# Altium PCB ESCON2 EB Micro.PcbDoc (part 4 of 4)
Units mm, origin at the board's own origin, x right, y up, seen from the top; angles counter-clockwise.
Board outline 75.6 x 72 mm, 8 copper layers (Top Side, Mid Layer 1, Mid Layer 2, Mid Layer 3, Mid Layer 4, Mid Layer 5, Mid Layer 6, Bottom Side), stack 1.555 mm thick; 192 components, 85 nets, 547 pads, 2387 vias.
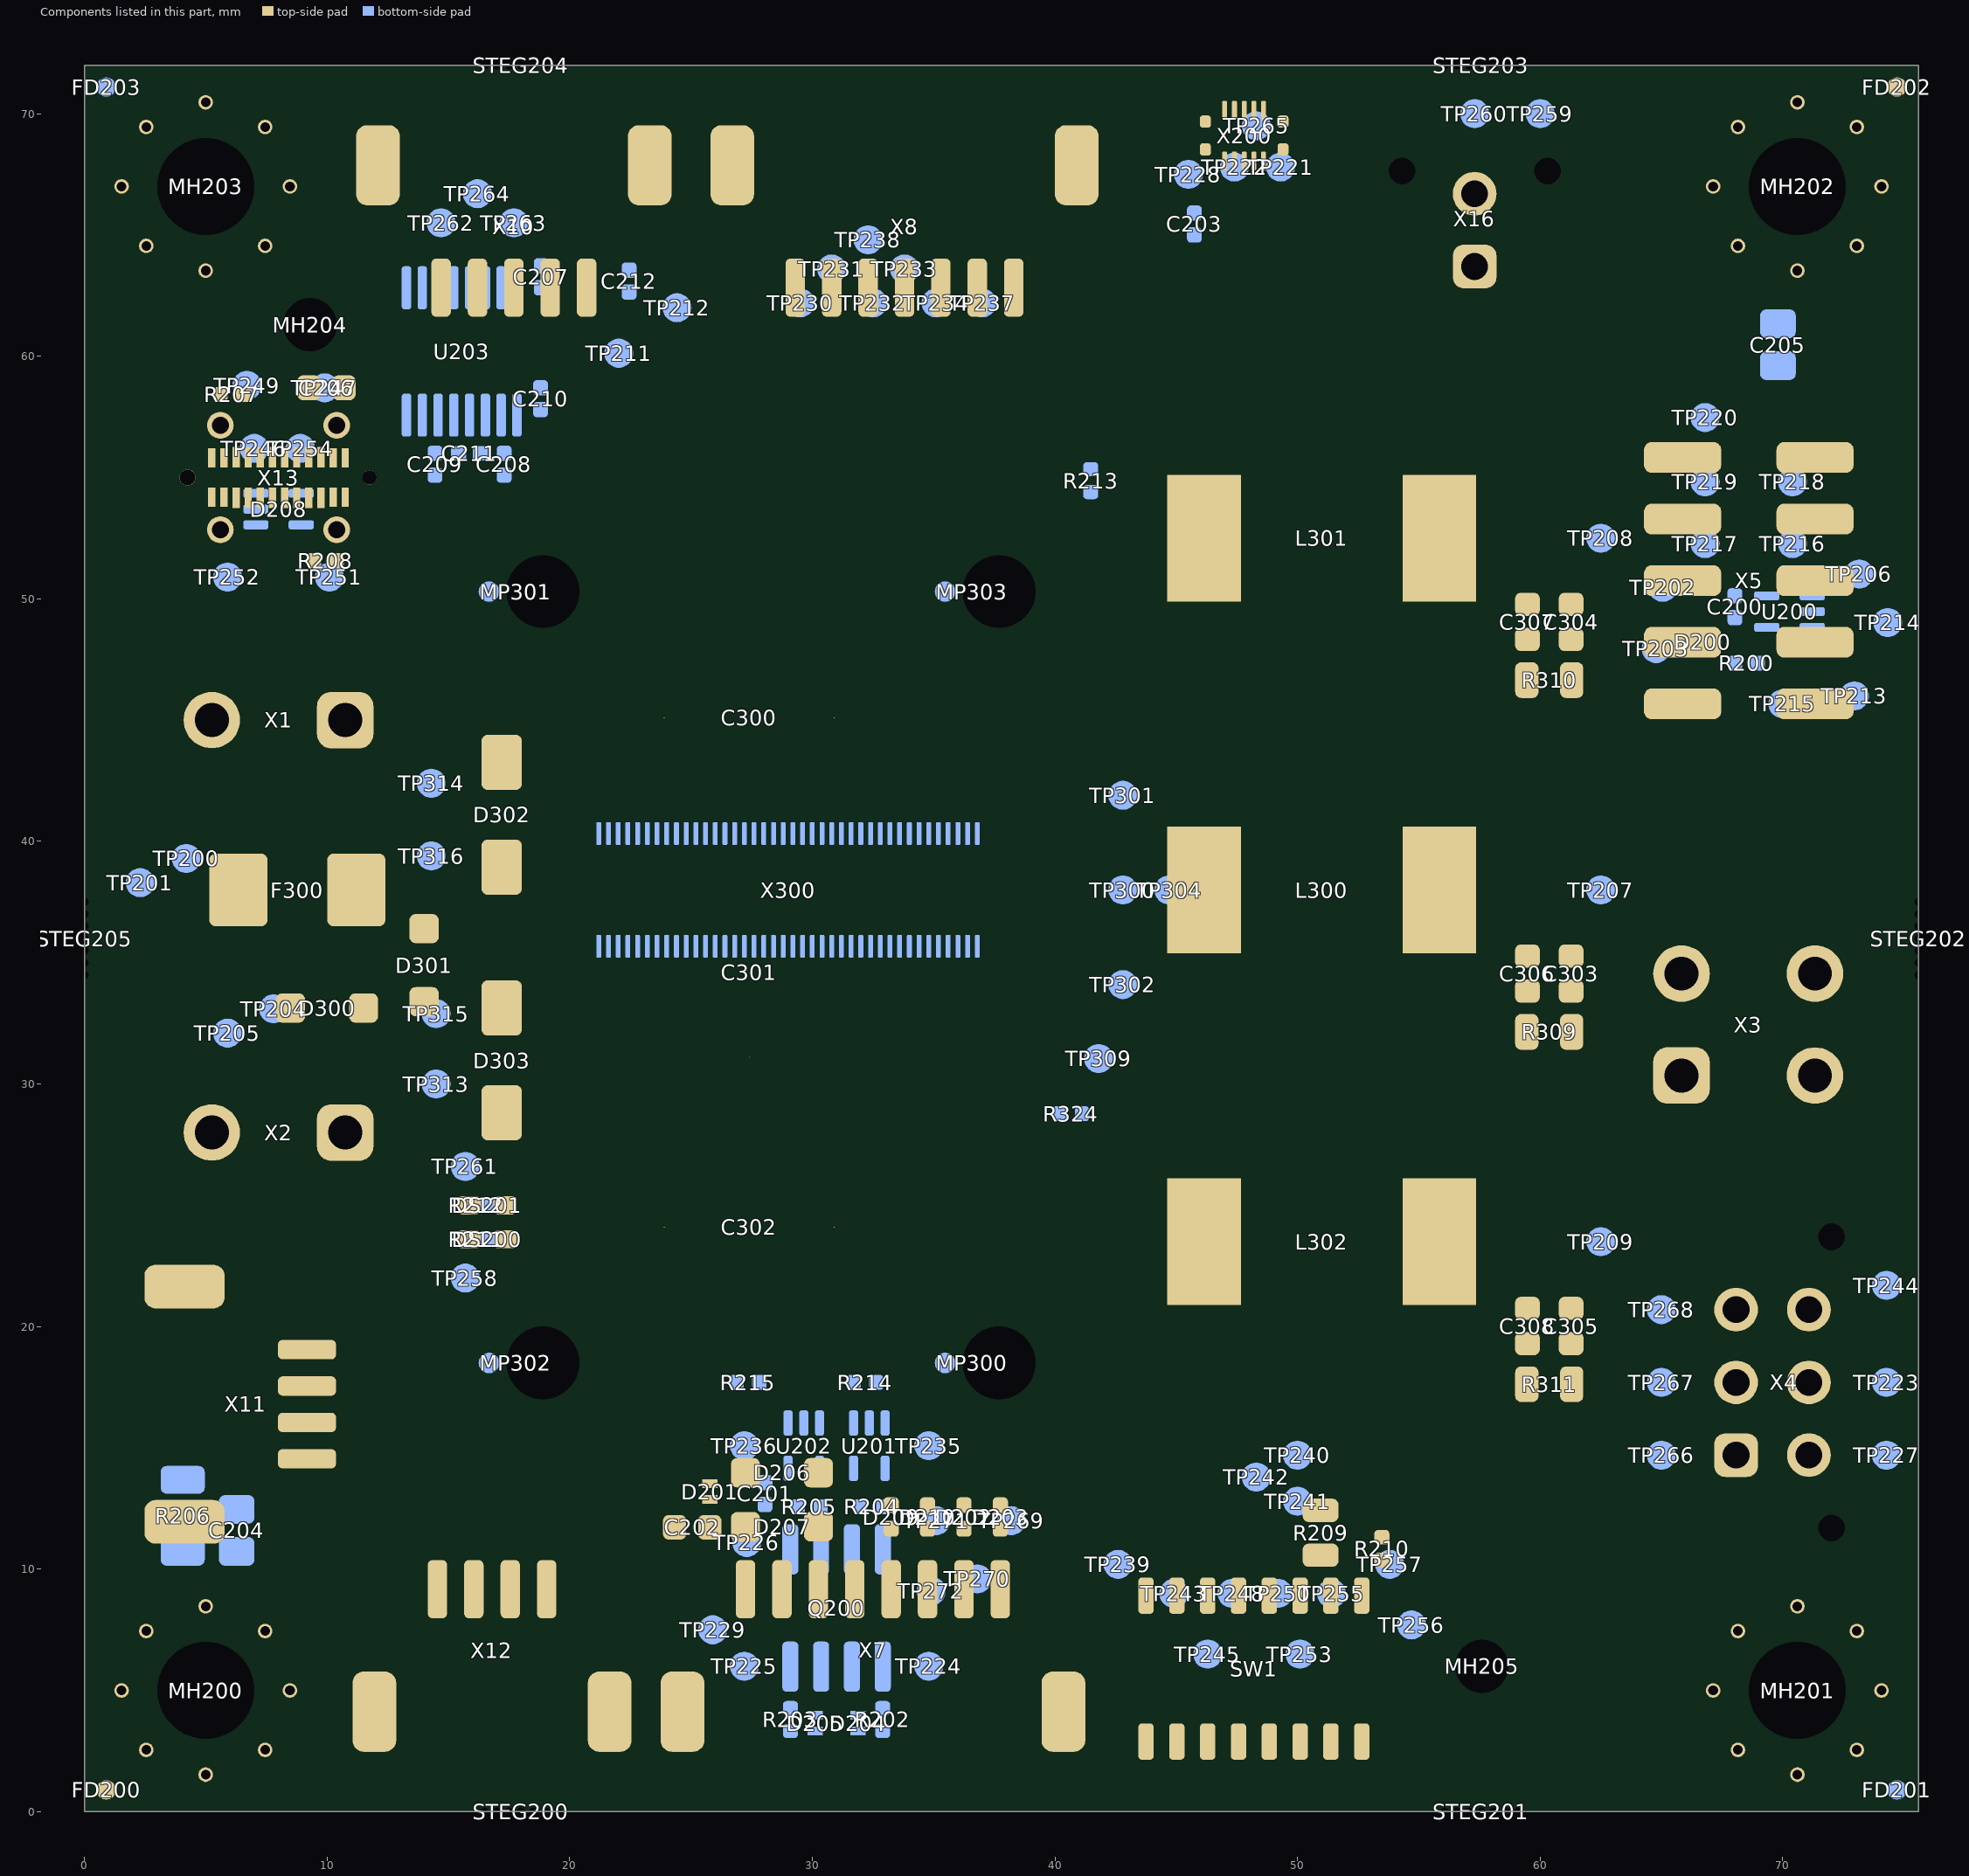
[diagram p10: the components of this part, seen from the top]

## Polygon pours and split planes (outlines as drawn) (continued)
GND on Bottom Side "B_GND-006" (solid, remove dead copper, pour order 220): 20.875,33.075 23.3,33.075 23.3,34.8 20.875,34.8
SGND on Bottom Side "B_SGND-003" (solid, pour order 327): 74.045,67 73.025,64.55 70.575,63.53 68.125,64.55 67.105,67 67.099,67 67.099,62.486 68.546,60.75 75.075,60.75 75.075,67
C_W2 on Bottom Side "B_C_W2-002" (solid, pour order 207): 68.275,41.325 63.475,41.325 63.475,46.125 65.475,46.125 cw(c65.488,43.338) 68.275,43.35
C_W2 on Bottom Side "B_C_W2-004" (solid, pour order 206): 59,46.125 63.8,46.125 63.8,41.325 61.8,41.325 cw(c61.787,44.112) 59,44.1
C_W2 on Bottom Side "B_C_W2-005" (solid, remove dead copper, pour order 176): 63.8,46 59,46 59,55.625 63.8,55.625
C_W1 on Bottom Side "B_C_W1-005" (solid, remove dead copper, pour order 199): 63.275,32.275 58.475,32.275 58.475,41.125 63.275,41.125
SGND on Bottom Side "B_SGND-002" (solid, pour order 318): 1.53,5 2.55,7.45 5,8.47 7.45,7.45 8.47,5 8.476,5 8.476,7.849 8.475,7.85 7.5,11.4 0.5,11.4 0.5,5
GND on Bottom Side "B_GND-002" (solid, remove dead copper, pour order 230): 22.975,37.95 22.3,37.95 22.3,42.525 22.975,42.525
GND on Bottom Side "B_GND-004" (solid, remove dead copper, pour order 208): 21.225,42.525 22.975,42.525 22.975,41.2 21.225,41.2
C_W3 on Bottom Side "B_C_W3-003" (solid, remove dead copper, pour order 200): 68.5,27.35 68.5,22.55 63.7,22.55 62.373,21.223 59,21.228 59,22.55 59,27.35
C_W1 on Bottom Side "B_C_W1-004" (solid, pour order 202): 58.475,32.35 63.275,32.35 63.275,27.55 61.275,27.55 cw(c61.262,30.337) 58.475,30.325
C_W3 on Bottom Side "B_C_W3-002" (solid, pour order 204): 68.475,22.55 68.475,27.35 73.275,27.35 73.275,25.35 cw(c70.488,25.337) 70.5,22.55
W on Bottom Side "B_W_m-001" (solid, remove dead copper, pour order 23): 33.5,41 34.5,41 34.5,30.275 33.5,30.275
V on Bottom Side "B_V_m-001" (solid, remove dead copper, pour order 22): 34.7,45.725 35.7,45.725 35.7,35 34.7,35
W on Bottom Side "B_W_m-002" (solid, remove dead copper, pour order 80): 33.5,30.275 37.9,30.275 37.9,34.796 33.5,34.796
V on Bottom Side "B_V_m-002" (solid, remove dead copper, pour order 28): 33.5,45.725 37.9,45.725 37.9,41.204 33.5,41.204
U on Bottom Side "B_U_m-001" (solid, remove dead copper, pour order 19): 35.9,41 37.9,41 37.9,35 35.9,35
GND on Mid Layer 6 "M6_GND-001" (solid, remove dead copper, pour order 332): 0,0 0,72 75.575,72 75.575,0
SGND on Mid Layer 6 "M6_SGND-001" (solid, remove dead copper, pour order 316): 68.675,37.35 73.275,37.35 73.275,32.55 68.675,32.55
C_VP on Mid Layer 6 "M6_C_VP-001" (solid, remove dead copper, pour order 315): 7.9,42.2 0,42.2 0,47.8 7.9,47.8
C_W1 on Mid Layer 6 "M6_C_W1-003" (solid, pour order 189): 68.275,32.35 68.275,27.55 63.225,27.55 63.225,32.35
C_W3 on Mid Layer 6 "M6_C_W3-001" (solid, remove dead copper, pour order 171): 68.475,32.35 73.275,32.35 73.275,27.225 68.475,27.225
C_W2 on Mid Layer 6 "M6_C_W2-001" (solid, remove dead copper, pour order 166): 68.275,41.5 68.275,32.55 63.475,32.55 63.475,41.5
GND on Mid Layer 6 "M6_GND-003" (solid, remove dead copper, pour order 221): 22.3,38 23.3,38 23.3,33.075 22.3,33.075
C_W2 on Mid Layer 6 "M6_C_W2-002" (solid, pour order 195): 68.275,41.325 63.475,41.325 63.475,46.125 65.475,46.125 cw(c65.488,43.338) 68.275,43.35
C_W2 on Mid Layer 6 "M6_C_W2-004" (solid, pour order 194): 59,46.125 63.8,46.125 63.8,41.325 61.8,41.325 cw(c61.787,44.112) 59,44.1
C_W2 on Mid Layer 6 "M6_C_W2-005" (solid, remove dead copper, pour order 44): 63.8,46 59,46 59,55.625 63.8,55.625
C_W3 on Mid Layer 6 "M6_C_W3-002" (solid, pour order 192): 68.475,22.55 68.475,27.35 73.275,27.35 73.275,25.35 cw(c70.488,25.337) 70.5,22.55
VP on Mid Layer 6 "M6_VP_m-001" (solid, remove dead copper, pour order 209): 19.6,41 22.1,41 22.1,35 19.6,35
GND on Mid Layer 6 "M6_GND-005" (solid, remove dead copper, pour order 224): 20.875,33.075 23.3,33.075 23.3,34.8 20.875,34.8
GND on Mid Layer 6 "M6_GND-002" (solid, remove dead copper, pour order 222): 22.975,37.95 22.3,37.95 22.3,42.525 22.975,42.525
GND on Mid Layer 6 "M6_GND-004" (solid, remove dead copper, pour order 223): 21.225,42.525 22.975,42.525 22.975,41.2 21.225,41.2
C_W1 on Mid Layer 6 "M6_C_W1-005" (solid, remove dead copper, pour order 181): 63.275,32.275 58.475,32.275 58.475,41.125 63.275,41.125
C_W3 on Mid Layer 6 "M6_C_W3-003" (solid, remove dead copper, pour order 188): 68.5,27.35 68.5,22.55 63.7,22.55 62.364,21.214 59,21.225 59,22.55 59,27.35
C_W1 on Mid Layer 6 "M6_C_W1-004" (solid, pour order 190): 58.475,32.35 63.275,32.35 63.275,27.55 61.275,27.55 cw(c61.262,30.337) 58.475,30.325
U on Mid Layer 6 "M6_U_m-001" (solid, remove dead copper, pour order 38): 35.9,41 37.9,41 37.9,35 35.9,35
V on Mid Layer 6 "M6_V_m-001" (solid, remove dead copper, pour order 0): 34.7,45.725 35.7,45.725 35.7,35 34.7,35
W on Mid Layer 6 "M6_W_m-002" (solid, remove dead copper, pour order 31): 33.5,30.275 37.9,30.275 37.9,34.796 33.5,34.796
V on Mid Layer 6 "M6_V_m-002" (solid, remove dead copper, pour order 30): 33.5,45.725 37.9,45.725 37.9,41.204 33.5,41.204
W on Mid Layer 6 "M6_W_m-001" (solid, remove dead copper, pour order 2): 33.5,41 34.5,41 34.5,30.275 33.5,30.275
GND on Top Side "T_GND-001" (solid, remove dead copper, pour order 321): 0,0 0,72 75.575,72 75.575,0
SGND on Top Side "T_SGND-001" (solid, remove dead copper, pour order 309): 68.675,37.35 73.275,37.35 73.275,32.55 68.675,32.55
C_VP on Top Side "T_C_VP-001" (solid, remove dead copper, pour order 305): 7.9,40.95 1.9,40.95 1.9,47.8 7.9,47.8
C_VL on Top Side "T_C_VL_-002" (solid, remove dead copper, pour order 297): 7.9,25.2 3.1,25.2 3.1,31.525 7.9,31.525
C_W2 on Top Side "T_C_W2-004" (solid, remove dead copper, pour order 163): 63.475,37.35 68.275,37.35 68.275,32.55 63.475,32.55
C_W3 on Top Side "T_C_W3-004" (solid, remove dead copper, pour order 162): 68.475,32.35 73.275,32.35 73.275,27.55 68.475,27.55
C_W1 on Top Side "T_C_W1-004" (solid, remove dead copper, pour order 161): 63.475,32.35 68.275,32.35 68.275,27.55 63.475,27.55
W on Top Side "T_W_m-003" (solid, pour order 135): 43.15,34.796 43.15,30.275 47.675,30.275 47.675,32.256 ccw(c45.135,32.256) 45.135,34.796
W on Top Side "T_W_m-004" (solid, remove dead copper, pour order 134): 44.45,20.5 41.675,23.275 41.675,30.3 47.675,30.3 47.675,20.5
V on Top Side "T_V_m-003" (solid, pour order 132): 43.15,41.204 43.15,45.725 47.675,45.725 47.675,43.744 cw(c45.135,43.744) 45.135,41.204
C_W2 on Top Side "T_C_W2-001" (solid, remove dead copper, pour order 43): 62.4,49.5 54.325,49.5 54.325,55.5 62.4,55.5
C_W1 on Top Side "T_C_W1-001" (solid, remove dead copper, pour order 42): 62.3,35 54.325,35 54.325,41 62.3,41
C_W3 on Top Side "T_C_W3-001" (solid, remove dead copper, pour order 41): 62.4,20.5 54.325,20.5 54.325,26.5 62.4,26.5
V on Top Side "T_V_m-004" (solid, remove dead copper, pour order 34): 44.45,55.5 41.675,52.725 41.675,45.675 47.675,45.675 47.675,55.5
U on Top Side "T_U_m-001" (solid, remove dead copper, pour order 25): 35.9,41 49.675,41 49.675,35 35.9,35
VP on Top Side "T_VP_m-001" (solid, remove dead copper, pour order 295): 22.1,35 8.875,35 8.875,41 22.1,41
C_VP on Top Side "T_C_VP-002" (solid, remove dead copper, pour order 303): 1.9,37.54 ccw(c4.44,37.54) 4.44,35 8.675,35 8.675,41 1.9,41
C_VL on Top Side "T_C_VL_-001" (solid, remove dead copper, pour order 298): 9.925,31.495 6.35,31.495 6.35,34.795 9.925,34.795
C_VL on Top Side "T_C_VL_-001" (solid, pour order 300): 6.4,34.795 6.4,31.495 3.105,31.495 3.1,31.5 3.1,32.255 cw(c5.64,32.255) 5.64,34.795
VL on Top Side "T_VL_m-001" (solid, remove dead copper, pour order 294): 10.075,34.775 19.398,34.775 19.398,31.475 10.075,31.475
VP on Top Side "T_VP_m-009" (solid, pour order 255): 21.6,46.1 21.6,44.1 26.15,44.1 26.15,46.1
VP on Top Side "T_VP_m-008" (solid, pour order 232): 26.4,29.475 28.4,29.475 28.4,33.35 26.4,33.35
VP on Top Side "T_VP_m-005" (solid, pour order 267): 26.4,27.525 26.4,29.525 28.4,29.525 cw(c26.4,29.525)
VP on Top Side "T_VP_m-004" (solid, pour order 259): 19.6,29.525 19.6,27.525 26.4,27.525 26.4,29.525
VP on Top Side "T_VP_m-007" (solid, pour order 231): 21.6,25.1 21.6,23.1 26.15,23.1 26.15,25.1
VP on Top Side "T_VP_m-006" (solid, pour order 268): 19.6,25.1 21.6,25.1 21.6,23.1 cw(c21.6,25.1)
VP on Top Side "T_VP_m-002" (solid, remove dead copper, pour order 225): 19.6,44.1 22.1,44.1 22.1,25.1 19.6,25.1
VP on Top Side "T_VP_m-003" (solid, pour order 263): 19.6,44.1 21.6,44.1 21.6,46.1 ccw(c21.6,44.1)
W on Top Side "T_W_m-002" (solid, remove dead copper, pour order 133): 33.5,30.275 45.2,30.275 45.2,34.796 33.5,34.796
V on Top Side "T_V_m-002" (solid, remove dead copper, pour order 32): 33.5,45.725 45.2,45.725 45.2,41.204 33.5,41.204
W on Top Side "T_W_m-001" (solid, remove dead copper, pour order 24): 33.5,41 34.5,41 34.5,30.275 33.5,30.275
V on Top Side "T_V_m-001" (solid, remove dead copper, pour order 10): 34.7,45.725 35.7,45.725 35.7,35 34.7,35
GND on Mid Layer 4 "M4_GND-001" (solid, remove dead copper, pour order 336): 0,0 0,72 75.575,72 75.575,0
C_VP on Mid Layer 4 "M4_C_VP-001" (solid, remove dead copper, pour order 314): 7.9,42.2 3.1,42.2 3.1,47.8 7.9,47.8
SGND on Mid Layer 4 "M4_SGND-001" (solid, remove dead copper, pour order 183): 68.675,37.35 73.275,37.35 73.275,32.55 68.675,32.55
C_W3 on Mid Layer 4 "M4_C_W3-002" (solid, remove dead copper, pour order 178): 68.475,32.35 73.275,32.35 73.275,27.55 68.475,27.55
C_W2 on Mid Layer 4 "M4_C_W2-002" (solid, remove dead copper, pour order 173): 63.475,37.35 68.275,37.35 68.275,32.55 63.475,32.55
C_W1 on Mid Layer 4 "M4_C_W1-002" (solid, remove dead copper, pour order 168): 63.475,32.35 68.275,32.35 68.275,27.55 63.475,27.55
VP on Mid Layer 4 "M4_VP_m-001" (solid, remove dead copper, pour order 233): 19.6,41 22.1,41 22.1,35 19.6,35
C_W3 on Mid Layer 4 "M4_C_W3-001" (solid, remove dead copper, pour order 153): 61.4,21.675 59.35,21.675 59.35,25.575 61.4,25.575
C_W1 on Mid Layer 4 "M4_C_W1-001" (solid, remove dead copper, pour order 152): 61.4,36.2 59.35,36.2 59.35,40.1 61.4,40.1
C_W2 on Mid Layer 4 "M4_C_W2-001" (solid, remove dead copper, pour order 151): 61.4,50.7 59.35,50.7 59.35,54.6 61.4,54.6
GND on Mid Layer 4 "M4_GND-002" (solid, remove dead copper, pour order 235): 22.975,37.95 22.3,37.95 22.3,42.525 22.975,42.525
GND on Mid Layer 4 "M4_GND-003" (solid, remove dead copper, pour order 234): 22.3,38 23.3,38 23.3,33.075 22.3,33.075
U on Mid Layer 4 "M4_U_m-001" (solid, remove dead copper, pour order 39): 35.9,41 37.9,41 37.9,35 35.9,35
W on Mid Layer 4 "M4_W_m-001" (solid, remove dead copper, pour order 15): 33.5,41 34.5,41 34.5,30.275 33.5,30.275
V on Mid Layer 4 "M4_V_m-001" (solid, remove dead copper, pour order 14): 34.7,45.725 35.7,45.725 35.7,35 34.7,35
GND on Mid Layer 3 "M3_GND-001" (solid, remove dead copper, pour order 347): 0,0 0,72 75.575,72 75.575,0
C_VP on Mid Layer 3 "M3_C_VP-001" (solid, remove dead copper, pour order 313): 7.9,42.2 0,42.2 0,47.8 7.9,47.8
SGND on Mid Layer 3 "M3_SGND-001" (solid, remove dead copper, pour order 184): 68.675,37.35 73.275,37.35 73.275,32.55 68.675,32.55
C_W3 on Mid Layer 3 "M3_C_W3-002" (solid, remove dead copper, pour order 179): 68.475,32.35 73.275,32.35 73.275,27.55 68.475,27.55
C_W2 on Mid Layer 3 "M3_C_W2-002" (solid, remove dead copper, pour order 174): 63.475,37.35 68.275,37.35 68.275,32.55 63.475,32.55
C_W1 on Mid Layer 3 "M3_C_W1-002" (solid, remove dead copper, pour order 169): 63.475,32.35 68.275,32.35 68.275,27.55 63.475,27.55
VP on Mid Layer 3 "M3_VP_m-001" (solid, remove dead copper, pour order 236): 19.6,41 22.1,41 22.1,35 19.6,35
C_W3 on Mid Layer 3 "M3_C_W3-001" (solid, remove dead copper, pour order 150): 61.4,21.675 59.35,21.675 59.35,25.575 61.4,25.575
C_W1 on Mid Layer 3 "M3_C_W1-001" (solid, remove dead copper, pour order 149): 61.4,36.2 59.35,36.2 59.35,40.1 61.4,40.1
C_W2 on Mid Layer 3 "M3_C_W2-001" (solid, remove dead copper, pour order 148): 61.4,50.7 59.35,50.7 59.35,54.6 61.4,54.6
GND on Mid Layer 3 "M3_GND-002" (solid, remove dead copper, pour order 238): 22.975,37.95 22.3,37.95 22.3,42.525 22.975,42.525
GND on Mid Layer 3 "M3_GND-003" (solid, remove dead copper, pour order 237): 22.3,38 23.3,38 23.3,33.075 22.3,33.075
U on Mid Layer 3 "M3_U_m-001" (solid, remove dead copper, pour order 1): 35.9,41 37.9,41 37.9,35 35.9,35
W on Mid Layer 3 "M3_W_m-001" (solid, remove dead copper, pour order 6): 33.5,41 34.5,41 34.5,30.275 33.5,30.275
V on Mid Layer 3 "M3_V_m-001" (solid, remove dead copper, pour order 4): 34.7,45.725 35.7,45.725 35.7,35 34.7,35
GND on Mid Layer 1 "M1_GND-001" (solid, remove dead copper, pour order 342): 0,0 0,72 75.575,72 75.575,0
C_VP on Mid Layer 1 "M1_C_VP-001" (solid, remove dead copper, pour order 302): 7.9,40.95 1.9,40.95 1.9,47.8 7.9,47.8
SGND on Mid Layer 1 "M1_SGND-001" (solid, remove dead copper, pour order 185): 68.675,37.35 73.275,37.35 73.275,32.55 68.675,32.55
C_W3 on Mid Layer 1 "M1_C_W3-004" (solid, remove dead copper, pour order 180): 68.475,32.35 73.275,32.35 73.275,27.55 68.475,27.55
C_W2 on Mid Layer 1 "M1_C_W2-004" (solid, remove dead copper, pour order 175): 63.475,37.35 68.275,37.35 68.275,32.55 63.475,32.55
C_W1 on Mid Layer 1 "M1_C_W1-004" (solid, remove dead copper, pour order 170): 63.475,32.35 68.275,32.35 68.275,27.55 63.475,27.55
U on Mid Layer 1 "M1_U_m-001" (solid, remove dead copper, pour order 7): 35.9,41 47.775,41 47.775,35 35.9,35
W on Mid Layer 1 "M1_W_m-002" (solid, remove dead copper, pour order 36): 33.5,30.25 43.45,30.25 43.45,34.8 33.5,34.8
V on Mid Layer 1 "M1_V_m-002" (solid, remove dead copper, pour order 17): 33.5,45.75 43.475,45.75 43.475,41.2 33.5,41.2
W on Mid Layer 1 "M1_W_m-003" (solid, pour order 213): 47.771,30.25 43.225,30.25 43.225,34.8 45.231,34.8 cw(c45.231,32.26) 47.771,32.26
W on Mid Layer 1 "M1_W_m-004" (solid, remove dead copper, pour order 212): 43.225,21.725 44.425,20.525 47.775,20.525 47.775,30.3 43.225,30.3
V on Mid Layer 1 "M1_V_m-003" (solid, pour order 211): 43.225,41.204 43.225,45.75 47.775,45.75 47.775,43.744 cw(c45.235,43.744) 45.235,41.204
V on Mid Layer 1 "M1_V_m-004" (solid, pour order 210): 43.225,54.275 44.425,55.475 47.775,55.475 47.775,45.7 43.225,45.7
C_W2 on Mid Layer 1 "M1_C_W2-001" (solid, remove dead copper, pour order 145): 62.4,49.5 54.275,49.5 54.275,55.5 62.4,55.5
C_W1 on Mid Layer 1 "M1_C_W1-001" (solid, remove dead copper, pour order 40): 62.4,35 54.275,35 54.275,41 62.4,41
C_W3 on Mid Layer 1 "M1_C_W3-001" (solid, remove dead copper, pour order 37): 62.35,20.5 54.275,20.5 54.275,26.5 62.35,26.5
C_VP on Mid Layer 1 "M1_C_VP-002" (solid, remove dead copper, pour order 306): 1.9,37.54 ccw(c4.44,37.54) 4.44,35 8.675,35 8.675,41 1.9,41
VP on Mid Layer 1 "M1_VP_m-009" (solid, remove dead copper, pour order 164): 22.1,35 8.875,35 8.875,41 22.1,41
VP on Mid Layer 1 "M1_VP_m-011" (solid, pour order 278): 19.6,25.1 21.6,25.1 21.6,23.1 cw(c21.6,25.1)
VP on Mid Layer 1 "M1_VP_m-010" (solid, pour order 277): 26.4,27.525 26.4,29.525 28.4,29.525 cw(c26.4,29.525)
VP on Mid Layer 1 "M1_VP_m-009" (solid, pour order 276): 19.6,44.1 21.6,44.1 21.6,46.1 ccw(c21.6,44.1)
VP on Mid Layer 1 "M1_VP_m-008" (solid, pour order 275): 19.6,29.525 19.6,27.525 26.4,27.525 28.4,29.525
VP on Mid Layer 1 "M1_VP_m-002" (solid, pour order 274): 21.6,46.1 21.6,44.1 26.15,44.1 26.15,46.1
VP on Mid Layer 1 "M1_VP_m-006" (solid, pour order 273): 26.4,29.475 28.4,29.475 28.4,33.35 26.4,33.35
VP on Mid Layer 1 "M1_VP_m-003" (solid, pour order 272): 21.6,25.1 21.6,23.1 26.15,23.1 26.15,25.1
VP on Mid Layer 1 "M1_VP_m-001" (solid, remove dead copper, pour order 271): 19.6,44.1 22.1,44.1 22.1,23.1 19.6,25.1
GND on Mid Layer 1 "M1_GND-005" (solid, pour order 266): 29.75,42.75 31.05,42.75 31.05,47.45 29.75,47.45
GND on Mid Layer 1 "M1_GND-004" (solid, pour order 265): 33.15,44.1 33.15,46.1 28.65,46.1 28.65,44.1
VP on Mid Layer 1 "M1_VP_m-004" (solid, pour order 264): 25.05,47.45 23.75,47.45 23.75,42.75 25.05,42.75
GND on Mid Layer 1 "M1_GND-007" (solid, pour order 262): 29.75,36.95 29.75,38.25 25.05,38.25 25.05,36.95
GND on Mid Layer 1 "M1_GND-006" (solid, pour order 261): 28.4,40.35 26.4,40.35 26.4,35.85 28.4,35.85
VP on Mid Layer 1 "M1_VP_m-007" (solid, pour order 260): 25.05,32.25 25.05,30.95 29.75,30.95 29.75,32.25
GND on Mid Layer 1 "M1_GND-009" (solid, pour order 258): 29.75,21.75 31.05,21.75 31.05,26.45 29.75,26.45
GND on Mid Layer 1 "M1_GND-008" (solid, pour order 257): 33.15,23.1 33.15,25.1 28.65,25.1 28.65,23.1
VP on Mid Layer 1 "M1_VP_m-005" (solid, pour order 256): 25.05,26.45 23.75,26.45 23.75,21.75 25.05,21.75
GND on Mid Layer 1 "M1_GND-002" (solid, remove dead copper, pour order 227): 22.975,37.95 22.3,37.95 22.3,42.525 22.975,42.525
GND on Mid Layer 1 "M1_GND-003" (solid, remove dead copper, pour order 226): 22.3,38 23.3,38 23.3,33.075 22.3,33.075
W on Mid Layer 1 "M1_W_m-001" (solid, remove dead copper, pour order 16): 33.5,41 34.5,41 34.5,30.275 33.5,30.275
V on Mid Layer 1 "M1_V_m-001" (solid, remove dead copper, pour order 13): 34.7,45.725 35.7,45.725 35.7,35 34.7,35
SGND on Mid Layer 2 "M2_SGND-001" (solid, remove dead copper, pour order 335): 0,0 0,72 75.575,72 75.575,0
GND on Mid Layer 2 "M2_GND-001" (solid, pour order 333): 5.001,8.46 8.47,5 67.105,5 70.575,8.47 70.575,63.53 67.105,67 8.47,67 5,63.53 5,8.47
SGND on Mid Layer 2 "M2_SGND-002" (solid, remove dead copper, pour order 325): 68.675,36.5 75.575,36.5 75.575,32.55 68.675,32.55
SGND on Mid Layer 2 "M2_SGND-003" (solid, remove dead copper, pour order 330): 0,57.7 10.95,57.7 10.95,52.3 0,52.3
SGND on Mid Layer 5 "M5_SGND-001" (solid, remove dead copper, pour order 334): 0,0 0,72 75.575,72 75.575,0
GND on Mid Layer 5 "M5_GND-001" (solid, pour order 331): 5.001,8.46 8.47,5 67.105,5 70.575,8.47 70.575,63.53 67.105,67 8.47,67 5,63.53 5,8.47
SGND on Mid Layer 5 "M5_SGND-002" (solid, remove dead copper, pour order 182): 68.675,36.5 75.575,36.5 75.575,32.55 68.675,32.55
SGND on Mid Layer 5 "M5_SGND-003" (solid, remove dead copper, pour order 328): 0,57.7 10.95,57.7 10.95,52.3 0,52.3

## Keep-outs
Top Side:
  region: 54.125,17.25 54.125,29.75 47.875,29.75 47.875,17.25
  region: 54.125,46.25 54.125,58.75 47.875,58.75 47.875,46.25
  region: 54.125,31.75 54.125,44.25 47.875,44.25 47.875,31.75

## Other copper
Top Side:
  text "'.Layer_Name'" at 100,70.355 h2
Mid Layer 1:
  text "'.Layer_Name'" at 100,68.375 h2
Mid Layer 2:
  text "'.Layer_Name'" at 100,66.375 h2
Mid Layer 3:
  text "'.Layer_Name'" at 100,64.375 h2
Mid Layer 6:
  text "'.Layer_Name'" at 100,58.375 h2
Mid Layer 4:
  text "'.Layer_Name'" at 100,62.375 h2
Mid Layer 5:
  text "'.Layer_Name'" at 100,60.375 h2
Bottom Side:
  pour cut-out: 22.975,39.85 33.3,39.85 33.3,36.15 23.375,36.15 23.375,38 22.975,38
  text "'.Layer_Name'" at 100,56.022 h2

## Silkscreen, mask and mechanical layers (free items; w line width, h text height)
Top Overlay:
  text "maxon" at 21,58.225 h2
  text "ESCON2 EB Micro" at 21,56.225 h2
  text "809646" at 21,54.225 h2
  text "'.Layer_Name'" at 100,46.375 h2
Bottom Overlay:
  lines w0.2: 17.3,21.84 17.3,46.96 ; 22.24,16.9 34.36,16.9 ; 22.24,51.9 34.36,51.9 ; 39.3,21.84 39.3,46.96
  text "ESCON2 Micro 60/5" at 16.9,47.025 h2 r90
  text "'.Layer_Name'" at 100,44.375 h2
  text "X300" at 19.15,39.525 h1.5 r90
Top Paste:
  text "'.Layer_Name'" at 100,50.355 h2
Bottom Paste:
  text "'.Layer_Name'" at 100,48.02 h2
Top Solder:
  text "'.Layer_Name'" at 100,54.355 h2
Bottom Solder:
  text "'.Layer_Name'" at 100,52.022 h2
  text "maxon" at 65.15,5.1 h2
  text ".PCB_raw" at 65.15,1.1 h2
Board:
  the board outline again, w0.1
  text "'.Layer_Name'" at 100,42.02 h2
Dimensions:
  text "'.Layer_Name'" at 100,40.02 h2
Sheet:
  drawing of 22 lines, arcs and shapes, not listed
  text "'.Layer_Name'" at 100,12.022 h2
  text "'.Application_BuildNumber'" at 1.475,-25.712 h1.5
  text "PCB P/N" at 41.728,-25.958 h2.5
  text "date:" at 9.529,-26.15 h2
  text "name:" at 24.479,-26.15 h2
  text "created" at 1.004,-28.848 h2
  text "18.08.2023" at 9.404,-29.075 h3
  text "HIN" at 24.341,-29.075 h3
  text "'.PCB_raw'" at 42.054,-30.725 h6
  text "modified" at 1.004,-31.896 h2
  text "26.03.2024" at 9.404,-32.114 h3
  text "HIN" at 24.341,-32.114 h3
  text "Fabrication Data and Revision" at 41.728,-34.085 h2.5
  text "Date" at 98.63,-34.11 h2.5
  text "reviewed" at 1.004,-34.946 h2
  text "26.03.2024" at 9.404,-35.164 h3
  text "WAH" at 24.341,-35.164 h3
  text "'.Print_Date'" at 99.13,-36.81 h2.5
  text "CO-no." at 1.104,-38.377 h2.5
  text "'.CO_no'" at 8.904,-38.4 h3
  text "'.Print_Time'" at 99.13,-39.035 h2.5
  text "'.ItemAndRevision'" at 42.054,-39.275 h6
  text "Variant P/N" at 41.73,-43.685 h2.5
  text "'.VariantName'" at 41.815,-47.52 h5.4
  text "File:" at 41.604,-51.7 h2.5
  text ".Department" at 17.279,-51.775 h3
  text "'.Pcb_File_Name_No_Path'" at 46.28,-51.785 h2.5
Assembly Notes:
  text "'.Layer_Name'" at 99.998,-3.625 h2
Fab Notes:
  text "'.Layer_Name'" at 100,-5.98 h2
V Cut:
  text "'.Layer_Name'" at 100.002,34.022 h2
Top Assembly:
  text "'.Layer_Name'" at 100,28.375 h2
Bottom Assembly:
  text "'.Layer_Name'" at 100,26.375 h2
Top 3D Body:
  text "'.Layer_Name'" at 100,24.375 h2
Bottom 3D Body:
  text "'.Layer_Name'" at 100,22.375 h2
Top Courtyard:
  text "'.Layer_Name'" at 100,16.375 h2
Bottom Courtyard:
  text "'.Layer_Name'" at 100,14.375 h2
Top Component Outline:
  text "'.Layer_Name'" at 100,20.355 h2
Bottom Component Outline:
  text "'.Layer_Name'" at 100,18.355 h2
Top Terminal:
  text "'.Layer_Name'" at 100,10.355 h2
Bottom Terminal:
  text "'.Layer_Name'" at 100,8.02 h2
Top Test:
  text "'.Layer_Name'" at 100,6.355 h2
Bottom Test:
  text "'.Layer_Name'" at 100,4.02 h2
Top Thermal:
  text "'.Layer_Name'" at 100,2.355 h2
Bottom Thermal:
  text "'.Layer_Name'" at 100,0.02 h2
Top Coating:
  text "'.Layer_Name'" at 100,38.375 h2
Bottom Coating:
  text "'.Layer_Name'" at 100,36.375 h2
Top Designator:
  text "'.Layer_Name'" at 100,32.375 h2
Bottom Designator:
  text "'.Layer_Name'" at 100,30.375 h2
Top Document Header:
  text "PCB P/N: '.PCB_raw'" at 100,-10 h2
  text "'.ItemAndRevision'" at 100,-11.98 h2
  text "Variant: '.VariantName'" at 100,-14 h2
  text "Variant Name: '.Variant_Description'" at 100,-16 h2
Bottom Document Header:
  text "PCB P/N: '.PCB_raw'" at 116,-10 h2
  text "'.ItemAndRevision'" at 116,-12 h2
  text "Variant: '.VariantName'" at 116,-14 h2
  text "Variant Name: '.Variant_Description'" at 116,-16 h2
Auxiliary Line:
  text "'.Layer_Name'" at 99.998,-1.625 h2

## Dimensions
75.6,0 to 18.9,50.3 on Dimensions
0,0 to 75.6,0 on Dimensions
75.6,0 to 18.9,18.5 on Dimensions
70.6,67 to 75.8,72.275 on Dimensions
9.3,61.3 to 6.025,64.9 on Dimensions
0,72 to 37.7,18.5 on Dimensions
0,72 to 18.9,18.5 on Dimensions
0,0 to 57.6,6 on Dimensions
0,0 to 70.6,67 on Dimensions
0,0 to 9.3,61.3 on Dimensions
0,0 to 5,67 on Dimensions
0,0 to 9.3,61.3 on Dimensions
0,0 to 57.6,6 on Dimensions
0,0 to 0,72 on Dimensions
0,0 to 70.6,67 on Dimensions
0,0 to 70.6,5 on Dimensions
